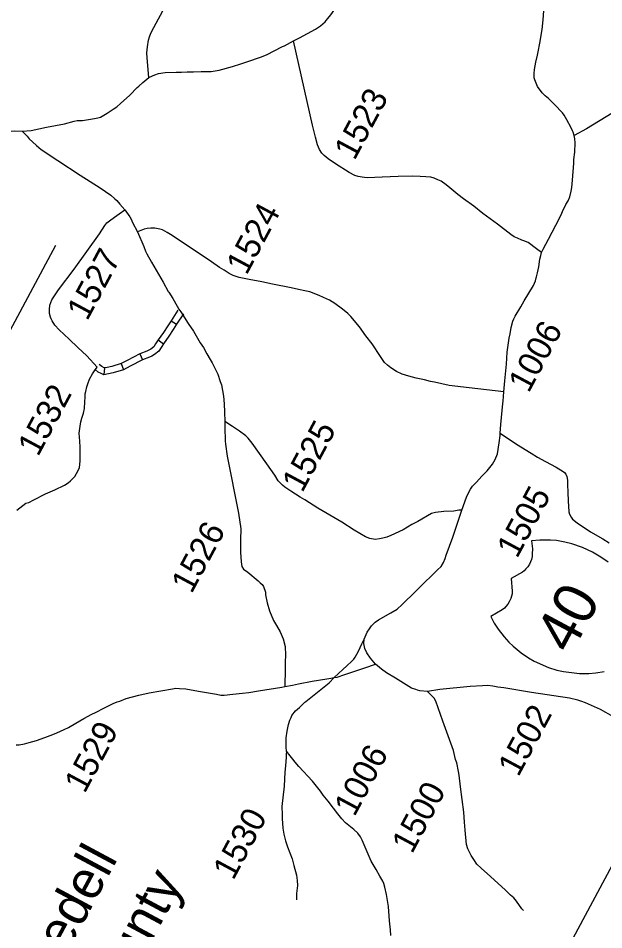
# Model space of a CAD drawing. Extents: x 1376167 to 1379209, y 761324 to 763997.
# Drawn here: x 1376608.1 to 1376708.2, y 762704.2 to 762860.1 of the extents above; entities that cross this region are included whole.
import ezdxf

# ---------------------------------------------------------------- set-up
doc = ezdxf.new("R2010")
doc.units = 0
doc.layers.add('Default', color=7, linetype='Continuous')
doc.layers.add('Old_Level_1', color=7, linetype='Continuous')

msp = doc.modelspace()

# ---------------------------------------------------------------- linework, layer by layer
at = {"layer": 'Default'}
for p, q in [((1376655.15, 762856.18), (1376656.18, 762856.74)), ((1376582.4, 762761.32), (1376614.56, 762821.29)), ((1376634.22, 762808.36), (1376635.16, 762807.74)), ((1376632.03, 762805.06), (1376632.96, 762804.42)), ((1376628.89, 762802.7), (1376629.35, 762801.67)), ((1376622.86, 762800.3), (1376622.73, 762799.13)), ((1376625.69, 762801.02), (1376626.12, 762799.97))]:
    msp.add_line(p, q, dxfattribs=at)
for points in [[(1376631.28, 762858.51), (1376634.78, 762864.99), (1376637.78, 762870.34), (1376639.28, 762873.13), (1376639.82, 762874.1), (1376641.16, 762876.68), (1376642.18, 762878.63)], [(1376656.18, 762856.74), (1376658.93, 762858.21), (1376659.77, 762858.78), (1376660.56, 762859.46), (1376660.74, 762859.67), (1376661.01, 762860), (1376661.51, 762860.66), (1376662.19, 762861.6), (1376662.92, 762862.41), (1376663.31, 762862.78), (1376663.82, 762863.12), (1376664.42, 762863.44), (1376664.87, 762863.68), (1376665.46, 762863.92), (1376666.03, 762864.06), (1376666.87, 762864.24), (1376670.21, 762865.34)], [(1376703.12, 762840.01), (1376702.95, 762840.58), (1376702.83, 762840.84), (1376702.57, 762841.36), (1376701.87, 762842.72), (1376701.39, 762843.51), (1376701.14, 762843.88), (1376699.75, 762845.34), (1376699.31, 762845.77), (1376698.7, 762846.34), (1376698.16, 762846.81), (1376697.63, 762847.34), (1376696.83, 762848.41), (1376696.48, 762849.25), (1376696.38, 762849.53), (1376696.29, 762849.86), (1376696.25, 762850.6), (1376696.32, 762851.29), (1376696.58, 762852.57), (1376696.82, 762853.73), (1376696.97, 762854.34), (1376697.23, 762855.81), (1376697.62, 762858.15), (1376697.79, 762859.81), (1376698.12, 762863.72)], [(1376630.44, 762849.91), (1376630.15, 762853.29), (1376630.09, 762854.15), (1376630.2, 762855.2), (1376630.38, 762856.31), (1376630.52, 762856.9), (1376630.77, 762857.53), (1376631.28, 762858.51)], [(1376630.44, 762849.91), (1376631.08, 762850.22), (1376631.47, 762850.39), (1376632.11, 762850.6), (1376633.21, 762850.78), (1376635.13, 762850.84), (1376635.99, 762850.86), (1376637.01, 762850.93), (1376638.07, 762850.91), (1376639.38, 762850.96), (1376641.08, 762850.98), (1376642.43, 762851.17), (1376644.74, 762851.83), (1376646.13, 762852.25), (1376647.36, 762852.66), (1376649.53, 762853.4), (1376650.52, 762853.83), (1376653.29, 762855.22), (1376653.59, 762855.37), (1376655.15, 762856.18)], [(1376697.55, 762820.03), (1376696.69, 762820.64), (1376695.27, 762821.7), (1376694.53, 762822.04), (1376694.17, 762822.15), (1376693.41, 762822.45), (1376692.87, 762822.7), (1376692.28, 762823.11), (1376690.02, 762824.86), (1376687.51, 762826.69), (1376685.97, 762827.93), (1376684.18, 762829.2), (1376683.21, 762829.95), (1376681.89, 762831.1), (1376681.25, 762831.61), (1376680.36, 762832.19), (1376679.8, 762832.47), (1376679.18, 762832.71), (1376678.59, 762832.87), (1376677.75, 762832.95), (1376676.82, 762832.99), (1376675.54, 762833.07), (1376673.03, 762833.03), (1376670.3, 762832.89), (1376667.77, 762832.78), (1376667.28, 762832.86), (1376666.86, 762832.91), (1376666.2, 762833.01), (1376665.63, 762833.21), (1376664.65, 762833.67), (1376662.34, 762835.18), (1376661.07, 762836.02), (1376660.37, 762836.61), (1376659.99, 762837.02), (1376659.62, 762837.61), (1376659.27, 762838.41), (1376658.92, 762839.71), (1376658.42, 762841.76), (1376655.15, 762856.18)], [(1376608.79, 762840.77), (1376610.33, 762840.89), (1376612.95, 762841.45), (1376616.03, 762842.02), (1376617.67, 762842.5), (1376618.17, 762842.56), (1376619.09, 762842.61), (1376621.13, 762842.92), (1376621.72, 762843.07), (1376622.15, 762843.18), (1376623.32, 762843.82), (1376624.34, 762844.51), (1376624.95, 762844.91), (1376625.58, 762845.47), (1376627.2, 762846.91), (1376628.43, 762848.22), (1376628.71, 762848.47), (1376629.4, 762849.06), (1376630.44, 762849.91)], [(1376723.09, 762846.45), (1376722.41, 762846.5), (1376721.57, 762846.58), (1376717.14, 762847.28), (1376716.46, 762847.3), (1376716.1, 762847.28), (1376715.52, 762847.15), (1376714.97, 762846.97), (1376712.98, 762845.91), (1376705.19, 762841.17), (1376703.12, 762840.01)], [(1376599.9, 762838.75), (1376601.09, 762839.11), (1376604.8, 762840.25), (1376606.05, 762840.61), (1376606.9, 762840.79), (1376607.53, 762840.82), (1376608.79, 762840.77)], [(1376608.79, 762840.77), (1376609.63, 762839.89), (1376610, 762839.44), (1376610.54, 762838.96), (1376611.25, 762838.29), (1376612.06, 762837.61), (1376614.86, 762835.74), (1376618.69, 762833.23)], [(1376700.87, 762826.48), (1376701.14, 762827.05), (1376701.71, 762828.2), (1376702.06, 762828.88), (1376702.35, 762829.55), (1376702.57, 762830.49), (1376702.71, 762831.14), (1376702.85, 762832.39), (1376703.08, 762835.28), (1376703.07, 762835.89), (1376703.2, 762837.18), (1376703.26, 762838.75), (1376703.23, 762839.44), (1376703.12, 762840.01)], [(1376618.69, 762833.23), (1376622.14, 762831.06), (1376623.94, 762829.82), (1376624.62, 762829.21), (1376624.98, 762828.9), (1376625.5, 762828.3), (1376626.32, 762827.29)], [(1376621.59, 762800.44), (1376619.83, 762802.35), (1376618.32, 762803.76), (1376616.81, 762805.2), (1376615.13, 762806.78), (1376614.38, 762807.59), (1376613.89, 762808.33), (1376613.74, 762808.66), (1376613.65, 762808.95), (1376613.47, 762809.6), (1376613.44, 762810.28), (1376613.53, 762811.04), (1376613.85, 762811.91), (1376614.41, 762812.77), (1376614.98, 762813.62), (1376617.67, 762817.19), (1376622, 762823.21), (1376622.92, 762824.61), (1376623.27, 762825.08), (1376623.73, 762825.42), (1376624.54, 762826.07), (1376625.36, 762826.64), (1376626.32, 762827.29)], [(1376626.32, 762827.29), (1376627.17, 762826.14), (1376627.42, 762825.69), (1376627.65, 762825.15), (1376628.47, 762823.53)], [(1376697.55, 762820.03), (1376697.8, 762820.57), (1376698.72, 762822.28), (1376699.97, 762824.67), (1376700.87, 762826.48)], [(1376691.07, 762796.17), (1376685.16, 762796.88), (1376681.77, 762797.3), (1376679.22, 762797.86), (1376678.54, 762797.98), (1376677.54, 762798.25), (1376676.1, 762798.56), (1376674.84, 762798.86), (1376673.73, 762799.21), (1376672.76, 762799.68), (1376671.78, 762800.28), (1376671.21, 762800.74), (1376670.72, 762801.22), (1376670.36, 762801.73), (1376670.01, 762802.24), (1376668.59, 762804.4), (1376667.53, 762805.79), (1376666.42, 762807.29), (1376664.93, 762809.09), (1376664.43, 762809.58), (1376663.53, 762810.35), (1376662.23, 762811.32), (1376661.31, 762811.85), (1376660.29, 762812.34), (1376659.56, 762812.68), (1376657.92, 762813.27), (1376657.11, 762813.49), (1376656.01, 762813.71), (1376654.75, 762813.95), (1376651.58, 762814.58), (1376649.72, 762815), (1376647.57, 762815.4), (1376645.87, 762815.76), (1376644.83, 762816.06), (1376644.13, 762816.4), (1376643.29, 762816.98), (1376642.52, 762817.47), (1376641.16, 762818.42), (1376634.44, 762822.93), (1376633.58, 762823.46), (1376632.75, 762823.87), (1376632.32, 762824.02), (1376631.46, 762824.17), (1376630.75, 762824.16), (1376630.13, 762824.11), (1376629.62, 762824), (1376628.47, 762823.53)], [(1376628.47, 762823.53), (1376629.58, 762821.05), (1376629.87, 762820.26), (1376630.1, 762819.77), (1376630.88, 762818.34), (1376632.87, 762814.97), (1376633.76, 762813.36), (1376633.85, 762813.21), (1376634.52, 762812.15), (1376635.25, 762810.83), (1376635.54, 762810.34), (1376635.88, 762809.86)], [(1376696.48, 762815.2), (1376696.61, 762815.67), (1376696.67, 762815.87), (1376696.83, 762816.53), (1376697.06, 762817.56), (1376697.26, 762818.86), (1376697.41, 762819.53), (1376697.55, 762820.03)], [(1376691.07, 762796.17), (1376691.25, 762798.09), (1376691.55, 762800.94), (1376691.68, 762803), (1376692, 762805.35), (1376692.16, 762806.11), (1376692.35, 762807.18), (1376692.65, 762808.29), (1376692.78, 762808.66), (1376693.04, 762809.15), (1376693.98, 762810.73), (1376694.59, 762811.76), (1376696.16, 762814.35), (1376696.48, 762815.2)], [(1376636.35, 762809.55), (1376635.16, 762807.74), (1376634.6, 762806.87), (1376633.86, 762805.74), (1376632.96, 762804.42), (1376632.52, 762803.76), (1376632.12, 762803.14), (1376631.42, 762802.57), (1376630.95, 762802.32), (1376630.54, 762802.11), (1376629.35, 762801.67), (1376627.24, 762800.58), (1376626.12, 762799.97), (1376624.36, 762799.44), (1376623.55, 762799.28), (1376622.73, 762799.13), (1376622.31, 762799.31), (1376621.8, 762799.58), (1376621.25, 762799.99)], [(1376635.41, 762810.17), (1376634.22, 762808.36), (1376633.65, 762807.48), (1376632.93, 762806.36), (1376632.03, 762805.06), (1376631.58, 762804.38), (1376631.27, 762803.9), (1376630.79, 762803.51), (1376630.42, 762803.31), (1376630.09, 762803.14), (1376628.89, 762802.7), (1376626.72, 762801.57), (1376625.69, 762801.02), (1376624.09, 762800.54), (1376623.33, 762800.38), (1376622.86, 762800.3), (1376622.8, 762800.32), (1376622.4, 762800.54), (1376621.93, 762800.89)], [(1376635.88, 762809.86), (1376637.16, 762807.89), (1376638.07, 762806.56), (1376639.23, 762804.59), (1376639.75, 762803.78), (1376640.32, 762802.71), (1376640.9, 762801.72), (1376641.24, 762801.18), (1376641.44, 762800.8), (1376642.22, 762799.22), (1376642.64, 762797.95), (1376642.83, 762797.39), (1376643.03, 762796.44), (1376643.21, 762795.47), (1376643.29, 762794.13), (1376643.36, 762792.71), (1376643.44, 762791.14)], [(1376607.9, 762775.94), (1376609.4, 762777.14), (1376609.91, 762777.28), (1376610.77, 762777.74), (1376612.78, 762778.76), (1376614.39, 762779.47), (1376616.04, 762780.23), (1376616.64, 762780.62), (1376617.04, 762781), (1376617.77, 762781.73), (1376618.35, 762782.75), (1376618.57, 762783.28), (1376618.65, 762783.79), (1376618.7, 762784.39), (1376618.71, 762785.2), (1376618.68, 762786.73), (1376618.66, 762787.77), (1376618.55, 762789.15), (1376618.69, 762790.33), (1376618.82, 762791.07), (1376618.98, 762791.69), (1376619.24, 762792.53), (1376619.46, 762793.37), (1376619.51, 762794.46), (1376619.53, 762795.29), (1376619.58, 762795.83), (1376619.66, 762796.26), (1376619.83, 762797.03), (1376620, 762797.56), (1376620.29, 762798.39), (1376620.79, 762799.27), (1376621.15, 762799.79), (1376621.59, 762800.44)], [(1376690.46, 762789.15), (1376690.6, 762790.6), (1376690.92, 762794.21), (1376691, 762794.62), (1376691.07, 762796.17)], [(1376643.44, 762791.14), (1376643.43, 762790.09), (1376643.47, 762787.82), (1376643.53, 762787.25), (1376643.83, 762785.2)], [(1376683.9, 762775.95), (1376683.4, 762775.95), (1376682.54, 762775.81), (1376680.83, 762775.74), (1376679.39, 762775.56), (1376678.71, 762775.4), (1376676.39, 762774.04), (1376675.39, 762773.52), (1376673.87, 762772.62), (1376671.8, 762771.61), (1376671.12, 762771.36), (1376670.41, 762771.19), (1376669.86, 762771.04), (1376669.13, 762770.95), (1376668.21, 762771.11), (1376667.45, 762771.43), (1376665.52, 762772.53), (1376663.39, 762773.89), (1376659.29, 762776.29), (1376657.08, 762777.72), (1376656.29, 762778.2), (1376654.72, 762779.21), (1376653.67, 762779.9), (1376653.25, 762780.24), (1376652.52, 762781), (1376651.94, 762781.95), (1376650.58, 762783.91), (1376648.08, 762787.43), (1376647.4, 762788.26), (1376646.99, 762788.68), (1376645.91, 762789.5), (1376644.75, 762790.26), (1376643.44, 762791.14)], [(1376683.9, 762775.95), (1376684.73, 762778.18), (1376684.88, 762778.56), (1376685.37, 762779.56), (1376685.76, 762780.07), (1376686.4, 762780.73), (1376687.36, 762781.78), (1376688.23, 762782.7), (1376689.17, 762783.84), (1376689.59, 762784.6), (1376689.99, 762785.61), (1376690.31, 762787.5), (1376690.44, 762788.76), (1376690.46, 762789.15)], [(1376690.46, 762789.15), (1376693.25, 762787.23), (1376695.74, 762785.72), (1376696.87, 762785.05), (1376698.21, 762784.31)], [(1376643.83, 762785.2), (1376645.73, 762775.48), (1376646.15, 762772.78), (1376646.07, 762770.88), (1376646.09, 762768.8), (1376646.21, 762767.13), (1376646.3, 762766.33), (1376646.59, 762765.88), (1376647.32, 762765.34), (1376649.1, 762763.86)], [(1376698.21, 762784.31), (1376700.01, 762783.32), (1376701.21, 762782.58), (1376701.45, 762782.39), (1376701.71, 762782.13), (1376701.86, 762781.73), (1376701.95, 762781.09), (1376701.97, 762780.36), (1376702.02, 762778.96), (1376702.06, 762777.57), (1376702.17, 762775.68), (1376702.3, 762775.31), (1376702.59, 762774.77), (1376702.84, 762774.45), (1376703.62, 762773.81), (1376705.9, 762772.27), (1376707.98, 762771.05), (1376709.11, 762770.36)], [(1376681.26, 762768.3), (1376682.36, 762771.36), (1376683.9, 762775.95)], [(1376708.92, 762767.09), (1376707.67, 762767.93), (1376706.26, 762768.8), (1376704.56, 762769.58), (1376702.73, 762770.2), (1376701.54, 762770.49), (1376700.07, 762770.76), (1376699.09, 762770.85), (1376697.26, 762770.84), (1376695.8, 762770.74), (1376695.97, 762769.35), (1376695.96, 762768.51), (1376695.93, 762768.02), (1376695.79, 762767.56), (1376695.48, 762766.76), (1376695.2, 762766.29), (1376694.86, 762765.91), (1376694.58, 762765.58), (1376694.27, 762765.35), (1376692.34, 762764.29), (1376692.52, 762762.09), (1376692.49, 762761.66), (1376692.38, 762761.27), (1376692.29, 762760.88), (1376692.02, 762760.31), (1376691.78, 762759.89), (1376691.46, 762759.49), (1376691.21, 762759.19), (1376690.81, 762758.9), (1376688.86, 762757.8), (1376689.46, 762756.64), (1376690.11, 762755.6), (1376691.13, 762754.33), (1376691.97, 762753.42), (1376692.68, 762752.72), (1376694.06, 762751.58), (1376695.33, 762750.7), (1376696.26, 762750.16), (1376698.74, 762749.06), (1376700.14, 762748.64), (1376701.31, 762748.36), (1376704, 762748.05), (1376705.59, 762748.05), (1376706.79, 762748.14), (1376708.22, 762748.4)], [(1376667.22, 762753.9), (1376667.74, 762755.1), (1376668.11, 762755.69), (1376668.46, 762756.17), (1376669.12, 762756.8), (1376669.67, 762757.19), (1376671.81, 762758.39), (1376672.84, 762759.02), (1376673.73, 762759.83), (1376674.17, 762760.3), (1376675.52, 762761.63), (1376676.43, 762762.52), (1376677.5, 762763.56), (1376678.77, 762764.81), (1376679.78, 762765.78), (1376680.36, 762766.34), (1376680.79, 762767.02), (1376681.06, 762767.69), (1376681.26, 762768.3)], [(1376649.1, 762763.86), (1376649.47, 762763.54), (1376649.78, 762763.24), (1376650, 762762.92), (1376650.35, 762761.97), (1376650.39, 762761.51), (1376650.66, 762760.12), (1376651.03, 762758.76), (1376651.75, 762757.08), (1376652.25, 762756.22), (1376652.85, 762755.19), (1376653.4, 762753.96), (1376653.74, 762752.63), (1376653.76, 762751.19), (1376653.73, 762750.03), (1376653.74, 762748.85), (1376653.66, 762745.84)], [(1376662.12, 762747.35), (1376663.6, 762748.74), (1376664.28, 762749.33), (1376665.12, 762750.16), (1376665.44, 762750.48), (1376665.7, 762750.83), (1376666, 762751.36), (1376666.26, 762751.87), (1376666.8, 762753.09), (1376667.22, 762753.9)], [(1376669.17, 762749.63), (1376668.3, 762750.65), (1376667.67, 762751.58), (1376667.32, 762752.29), (1376667.19, 762753.19), (1376667.22, 762753.9)], [(1376662.12, 762747.35), (1376662.63, 762747.44), (1376663.94, 762747.86), (1376667.32, 762749), (1376669.17, 762749.63)], [(1376678.05, 762744.97), (1376676.76, 762745.09), (1376676.36, 762745.18), (1376676.03, 762745.29), (1376675.31, 762745.56), (1376672.6, 762747.24), (1376671.03, 762748.17), (1376670.19, 762748.76), (1376669.17, 762749.63)], [(1376653.66, 762745.84), (1376655, 762746.06), (1376656.01, 762746.25), (1376658.36, 762746.71), (1376660.83, 762747.12), (1376661.52, 762747.25), (1376662.12, 762747.35)], [(1376653.97, 762734.75), (1376653.91, 762735.44), (1376653.9, 762735.88), (1376653.87, 762736.31), (1376653.88, 762737.03), (1376654.05, 762738.17), (1376654.32, 762739.31), (1376654.52, 762740.05), (1376654.73, 762740.53), (1376654.89, 762740.84), (1376655.5, 762741.65), (1376656.16, 762742.25), (1376657.1, 762743.13), (1376657.25, 762743.27), (1376660.39, 762745.74), (1376661.24, 762746.46), (1376662.12, 762747.35)], [(1376607.75, 762735.87), (1376608.27, 762735.85), (1376609.16, 762736.01), (1376610, 762736.26), (1376611.22, 762736.61), (1376612.64, 762737.1), (1376614.05, 762737.62), (1376614.73, 762737.92), (1376615.97, 762738.49), (1376616.68, 762738.81), (1376617.95, 762739.54), (1376619.32, 762740.34), (1376620.71, 762741.07), (1376621.31, 762741.39), (1376622.86, 762742.19), (1376624.35, 762742.93), (1376625.03, 762743.18), (1376625.47, 762743.34), (1376626.56, 762743.77), (1376628.71, 762744.34), (1376630.48, 762744.71), (1376634.45, 762745.44), (1376635.06, 762745.52), (1376635.65, 762745.5), (1376636.74, 762745.41), (1376638.91, 762745.02), (1376642.02, 762744.49), (1376642.72, 762744.36), (1376643.31, 762744.33), (1376644.78, 762744.52), (1376646.44, 762744.69), (1376647.52, 762744.82), (1376649.18, 762745.06), (1376653.18, 762745.72), (1376653.66, 762745.84)], [(1376695.84, 762744.77), (1376691.09, 762745.6), (1376690.04, 762745.72), (1376689.22, 762745.89), (1376688.37, 762745.98), (1376687.45, 762745.93), (1376685.31, 762745.84), (1376680.13, 762745.32), (1376678.05, 762744.97)], [(1376694.45, 762707.52), (1376694.14, 762707.83), (1376693.28, 762709.14), (1376692.78, 762709.68), (1376692.22, 762710.17), (1376691.37, 762711.01), (1376688.82, 762713.36), (1376687.19, 762714.76), (1376686.48, 762715.44), (1376685.94, 762716.23), (1376685.51, 762716.93), (1376684.96, 762718.09), (1376684.71, 762718.8), (1376684.46, 762721.27), (1376684.38, 762722.62), (1376684.25, 762724.32), (1376683.68, 762728.68), (1376683.44, 762730.67), (1376683.32, 762731.31), (1376683.04, 762732.79), (1376682.86, 762733.33), (1376682.51, 762734.85), (1376681.37, 762738.02), (1376680.68, 762739.9), (1376679.48, 762743.32), (1376679.18, 762743.81), (1376678.76, 762744.22), (1376678.5, 762744.51), (1376678.05, 762744.97)], [(1376711.72, 762739.74), (1376711.34, 762739.91), (1376709.81, 762740.62), (1376707.6, 762741.86), (1376705.04, 762743.03), (1376704.42, 762743.27), (1376703.76, 762743.48), (1376702.3, 762743.82), (1376695.84, 762744.77)], [(1376653.97, 762734.75), (1376653.92, 762734.2), (1376653.9, 762733.74), (1376653.77, 762732.24), (1376653.66, 762731.16), (1376653.53, 762728.78), (1376653.13, 762725.28), (1376653.24, 762723.93), (1376653.23, 762723.23), (1376653.34, 762721.58), (1376653.5, 762720.59), (1376653.78, 762719.41), (1376654.14, 762718.38), (1376654.91, 762716.36), (1376655.21, 762715.23), (1376655.65, 762713.56), (1376655.77, 762712.64), (1376655.81, 762711.82), (1376655.64, 762710.41), (1376655.66, 762709.58), (1376655.69, 762709.37)], [(1376671.77, 762703.25), (1376671.74, 762704.23), (1376671.58, 762705.74), (1376671.39, 762708.23), (1376671.06, 762710.27), (1376670.78, 762711.53), (1376670.58, 762712.14), (1376670.42, 762712.51), (1376669.93, 762713.38), (1376669.26, 762714.55), (1376668.45, 762715.95), (1376666.87, 762719.57), (1376666.59, 762720.1), (1376666.13, 762720.75), (1376665.45, 762721.37), (1376664.06, 762722.52), (1376663.39, 762723.18), (1376662.7, 762724.06), (1376661.98, 762725.01), (1376661.05, 762726.2), (1376660.24, 762727.26), (1376659.78, 762727.91), (1376658.42, 762729.62), (1376656.07, 762732.16), (1376655.44, 762732.87), (1376655.03, 762733.37), (1376654.57, 762733.98), (1376653.97, 762734.75)]]:
    msp.add_lwpolyline(points, dxfattribs=at)
at = {"layer": 'Old_Level_1'}
msp.add_lwpolyline([(1376622.61, 762553.05), (1376345.79, 762701.47), (1376550.88, 763083.99), (1376827.7, 762935.57)], close=True, dxfattribs=at)

# ---------------------------------------------------------------- texts
at = {"layer": 'Default'}
msp.add_text('40', height=7.324, rotation=61.8015, dxfattribs=at).set_placement((1376702.58, 762751.14))
at = {"layer": 'Old_Level_1'}
for s, height, p in [('1523', 4.185, (1376665.57, 762835.61)), ('1524', 4.185, (1376647.13, 762816)), ('1527', 4.185, (1376619.9, 762808.19)), ('1006', 4.185, (1376695.33, 762795.85)), ('1532', 4.185, (1376611.5, 762784.98)), ('1525', 4.185, (1376656.65, 762778.81)), ('1505', 4.185, (1376693.35, 762767.57)), ('1526', 4.185, (1376637.73, 762761.54)), ('1502', 4.185, (1376693.56, 762730.22)), ('1529', 4.185, (1376619.46, 762727.38)), ('1006', 4.185, (1376665.56, 762723.41)), ('1500', 4.185, (1376675.4, 762717.06)), ('1530', 4.185, (1376644.86, 762712.55)), ('Iredell ', 6.539, (1376613.96, 762695.45)), ('County', 6.539, (1376623.24, 762687.85))]:
    msp.add_text(s, height=height, rotation=61.8015, dxfattribs=at).set_placement(p)

doc.saveas('drawing.dxf')
